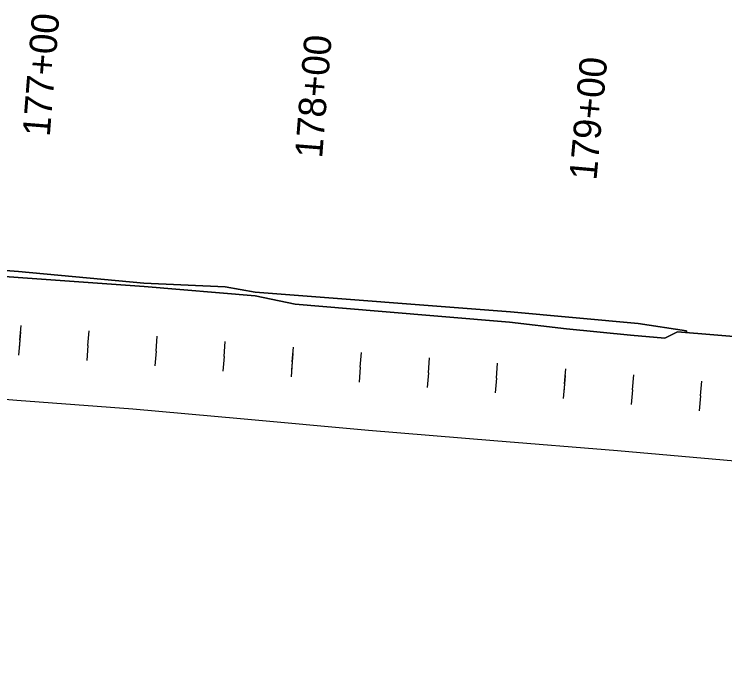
# Model space of a CAD drawing. Extents: x 20499880 to 20505309, y 7953507 to 7955507.
# Drawn here: x 20501407.8 to 20501667.8, y 7953801.6 to 7954043.9 of the extents above; entities that cross this region are included whole.
import ezdxf

# ---------------------------------------------------------------- set-up
doc = ezdxf.new("R2010")
doc.units = 0
for name, color, linetype in [('Alignment', 7, 'Continuous'), ('Curb', 7, 'Continuous'), ('Draft_0', 7, 'Continuous'), ('Entrance', 7, 'Continuous')]:
    doc.layers.add(name, color=color, linetype=linetype)

msp = doc.modelspace()

# ---------------------------------------------------------------- linework, layer by layer
at = {"layer": 'Alignment'}
for p, q in [((20501409.81, 7953924.47), (20501410.25, 7953929.91)), ((20501409.81, 7953924.47), (20501409.38, 7953919.03)), ((20501509.5, 7953916.55), (20501509.93, 7953921.99)), ((20501509.5, 7953916.55), (20501509.07, 7953911.11)), ((20501609.18, 7953908.55), (20501609.67, 7953913.99)), ((20501609.18, 7953908.55), (20501608.69, 7953903.12))]:
    msp.add_line(p, q, dxfattribs=at)
at = {"layer": 'Curb'}
for points in [[(20501653.78, 7953927.23), (20501653.77, 7953927.86), (20501636.16, 7953930.64), (20501589.4, 7953934.88), (20501495.94, 7953942.1), (20501484.96, 7953944.03), (20501455.22, 7953945.39), (20501409.27, 7953949.65), (20501370.2, 7953952.66), (20501321.27, 7953953.59), (20501287.99, 7953955.38), (20501244.51, 7953958.83), (20501199.67, 7953962.27), (20501153.86, 7953965.49), (20501109.17, 7953967.64), (20501081.81, 7953970.91), (20501065.07, 7953970.3), (20501044.25, 7953970.49), (20501021.55, 7953971.51), (20500974.87, 7953974.47), (20500954.52, 7953976.56), (20500954.89, 7953972.95)], [(20501722.29, 7953921.85), (20501677.12, 7953925.34), (20501650.59, 7953927.49), (20501645.85, 7953925.21), (20501633.38, 7953926.32), (20501609.89, 7953928.7), (20501589.06, 7953931.11), (20501540.94, 7953935.13), (20501510.62, 7953937.62), (20501495.91, 7953940.76), (20501455.36, 7953944.15), (20501410.85, 7953947.34), (20501367.41, 7953950.44)], [(20501717.61, 7953875.88), (20501671.53, 7953880.18), (20501628.56, 7953883.94), (20501583.34, 7953887.58), (20501537.38, 7953891.4), (20501490.63, 7953895.73), (20501451.22, 7953899.23), (20501408.69, 7953902.39), (20501365.27, 7953906.03), (20501318.62, 7953909.59), (20501303.35, 7953910.68), (20501300.71, 7953909.78), (20501299.38, 7953900.73), (20501299.61, 7953893.51), (20501300.21, 7953868.42), (20501300.22, 7953842.73), (20501300.2, 7953834.08), (20501300.49, 7953816.42), (20501301.22, 7953801.6)]]:
    msp.add_lwpolyline(points, dxfattribs=at)
at = {"layer": 'Draft_0'}
for points in [[(20501370.2, 7953952.66), (20501409.27, 7953949.65), (20501455.22, 7953945.39), (20501484.96, 7953944.03), (20501495.94, 7953942.1), (20501589.4, 7953934.88), (20501636.16, 7953930.64), (20501653.77, 7953927.86), (20501653.78, 7953927.23), (20501650.59, 7953927.49), (20501645.85, 7953925.21), (20501633.38, 7953926.32), (20501609.89, 7953928.7), (20501589.06, 7953931.11), (20501540.94, 7953935.13), (20501510.62, 7953937.62), (20501495.91, 7953940.76), (20501455.36, 7953944.15), (20501410.85, 7953947.34), (20501367.41, 7953950.44)], [(20501367.41, 7953950.44), (20501410.85, 7953947.34), (20501455.36, 7953944.15), (20501495.91, 7953940.76), (20501510.62, 7953937.62), (20501540.94, 7953935.13), (20501589.06, 7953931.11), (20501609.89, 7953928.7), (20501633.38, 7953926.32), (20501645.85, 7953925.21), (20501650.59, 7953927.49), (20501677.12, 7953925.34), (20501721.64, 7953921.9), (20501720.95, 7953917.54), (20501720.32, 7953912.11), (20501729.83, 7953909.97), (20501745.01, 7953908.18), (20501757, 7953907.33), (20501771.09, 7953906.16), (20501788.27, 7953904.85), (20501788.64, 7953907.48)], [(20501929.07, 7953862.02), (20501885.51, 7953866.8), (20501842, 7953870.66), (20501797.75, 7953874.36), (20501788.44, 7953875.07), (20501788.61, 7953875.21), (20501789.16, 7953878.47), (20501788.42, 7953878.6), (20501788.52, 7953880.56), (20501773.58, 7953882), (20501754.88, 7953883.71), (20501731.49, 7953885.96), (20501718.4, 7953887.04), (20501717.61, 7953875.88), (20501671.53, 7953880.18), (20501628.56, 7953883.94), (20501583.34, 7953887.58), (20501537.38, 7953891.4), (20501490.63, 7953895.73), (20501451.22, 7953899.23), (20501408.69, 7953902.39), (20501365.27, 7953906.03)]]:
    msp.add_lwpolyline(points, dxfattribs=at)
at = {"layer": 'Entrance'}
for p, q in [((20501434.74, 7953922.49), (20501435.17, 7953927.93)), ((20501410.06, 7953927.52), (20501409.57, 7953921.42)), ((20501410.06, 7953927.52), (20501409.57, 7953921.42)), ((20501459.66, 7953920.51), (20501460.09, 7953925.95)), ((20501484.58, 7953918.53), (20501485.01, 7953923.97)), ((20501434.74, 7953922.49), (20501434.3, 7953917.05)), ((20501459.66, 7953920.51), (20501459.22, 7953915.07)), ((20501484.58, 7953918.53), (20501484.15, 7953913.09)), ((20501509.74, 7953919.6), (20501509.26, 7953913.5)), ((20501509.74, 7953919.6), (20501509.26, 7953913.5)), ((20501534.42, 7953914.57), (20501534.85, 7953920.01)), ((20501559.34, 7953912.59), (20501559.78, 7953918.03)), ((20501584.26, 7953910.61), (20501584.7, 7953916.05)), ((20501534.42, 7953914.57), (20501533.99, 7953909.13)), ((20501559.34, 7953912.59), (20501558.91, 7953907.14)), ((20501584.26, 7953910.61), (20501583.83, 7953905.16)), ((20501609.45, 7953911.6), (20501608.91, 7953905.51)), ((20501609.45, 7953911.6), (20501608.91, 7953905.51)), ((20501634.08, 7953906.33), (20501634.57, 7953911.76)), ((20501658.98, 7953904.1), (20501659.47, 7953909.53)), ((20501634.08, 7953906.33), (20501633.59, 7953900.89)), ((20501658.98, 7953904.1), (20501658.49, 7953898.66))]:
    msp.add_line(p, q, dxfattribs=at)

# ---------------------------------------------------------------- texts
for s, rotation, p in [('177+00', 85.4564, (20501420.75, 7953998.84)), ('178+00', 85.4564, (20501520.44, 7953990.92)), ('179+00', 84.8834, (20501620.86, 7953982.81))]:
    msp.add_text(s, height=10.02, rotation=rotation, dxfattribs=at).set_placement(p)

doc.saveas('drawing.dxf')
